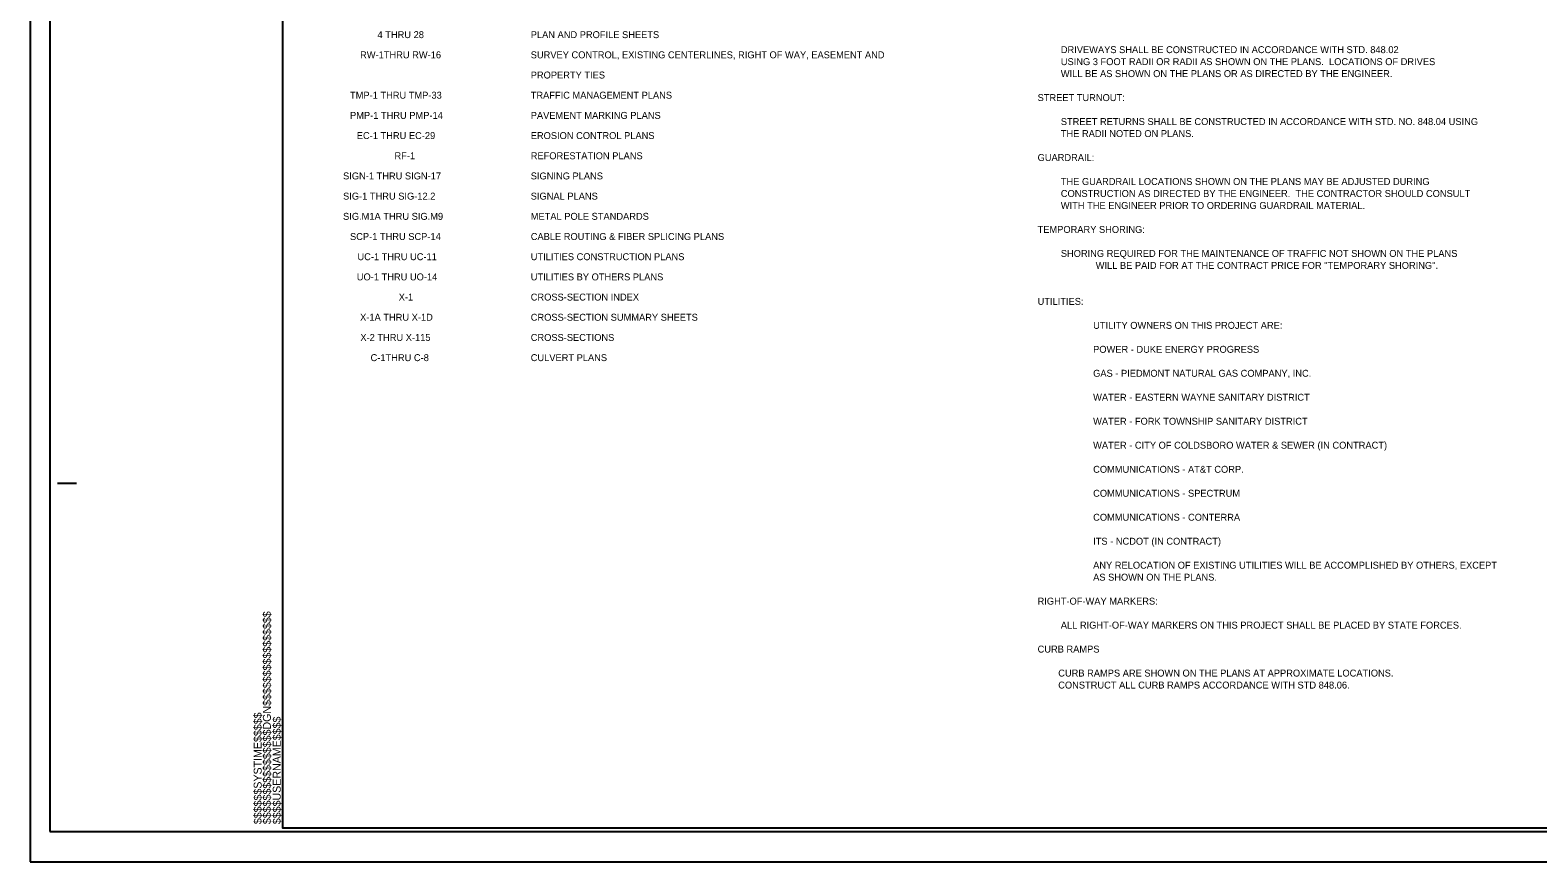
# Model space of a CAD drawing. Extents: x 1877070 to 1879304, y 464355 to 465670.
# Drawn here: x 1877070 to 1878265, y 464355 to 465014 of the extents above; entities that cross this region are included whole.
import ezdxf

# ---------------------------------------------------------------- set-up
doc = ezdxf.new("R2010")
doc.units = 0
for name, color, linetype in [('Prop AutoTurn Projected Path', 7, 'Continuous'), ('Prop Horizontal Alignment', 7, 'Continuous'), ('Prop Lane Lines', 7, 'Continuous'), ('Scratch_Level_0', 7, 'Continuous')]:
    doc.layers.add(name, color=color, linetype=linetype)

msp = doc.modelspace()

# ---------------------------------------------------------------- linework, layer by layer
at = {"layer": 'Prop AutoTurn Projected Path'}
msp.add_lwpolyline([(1877070, 464355.1), (1879090.8, 464355.1), (1879090.8, 465669.5), (1877070, 465669.5)], close=True, dxfattribs=at)
at = {"layer": 'Prop Lane Lines'}
msp.add_lwpolyline([(1877085.6, 464379.1), (1879085.4, 464379.1), (1879085.4, 465645.5), (1877085.6, 465645.5)], close=True, dxfattribs=at)
at = {"layer": 'Scratch_Level_0'}
for p, q in [((1877091.6, 464655.2), (1877106.6, 464655.2)), ((1877269.8, 464382.1), (1877269.8, 464382.1))]:
    msp.add_line(p, q, dxfattribs=at)
msp.add_lwpolyline([(1879070.4, 465642.5), (1877269.8, 465642.5), (1877269.8, 464382.1), (1879070.4, 464382.1)], close=True, dxfattribs=at)

# ---------------------------------------------------------------- texts
at = {"layer": 'Prop Horizontal Alignment'}
for s, p in [('4 THRU 28', (1877345.2, 465008)), ('PLAN AND PROFILE SHEETS', (1877466.6, 465008)), ('RW-1THRU RW-16', (1877331.4, 464992)), ('SURVEY CONTROL, EXISTING CENTERLINES, RIGHT OF WAY, EASEMENT AND ', (1877466.6, 464992)), ('         USING 3 FOOT RADII OR RADII AS SHOWN ON THE PLANS.  LOCATIONS OF DRIVES', (1877868.2, 464986.6)), ('         DRIVEWAYS SHALL BE CONSTRUCTED IN ACCORDANCE WITH STD. 848.02', (1877868.2, 464996.1)), ('PROPERTY TIES', (1877466.6, 464976)), ('         WILL BE AS SHOWN ON THE PLANS OR AS DIRECTED BY THE ENGINEER.  ', (1877868.2, 464977.1)), ('TMP-1 THRU TMP-33', (1877323.4, 464960)), ('TRAFFIC MANAGEMENT PLANS', (1877466.6, 464960)), ('STREET TURNOUT:  ', (1877868.2, 464958.1)), ('PMP-1 THRU PMP-14', (1877323.4, 464944)), ('PAVEMENT MARKING PLANS', (1877466.6, 464944)), ('         STREET RETURNS SHALL BE CONSTRUCTED IN ACCORDANCE WITH STD. NO. 848.04 USING ', (1877868.2, 464939.1)), ('EC-1 THRU EC-29', (1877328.8, 464928)), ('EROSION CONTROL PLANS', (1877466.6, 464928)), ('         THE RADII NOTED ON PLANS.  ', (1877868.2, 464929.6)), (' RF-1', (1877356.6, 464912)), ('REFORESTATION PLANS', (1877466.6, 464912)), ('GUARDRAIL:  ', (1877868.2, 464910.6)), ('SIGN-1 THRU SIGN-17', (1877317.9, 464896)), ('SIGNING PLANS', (1877466.6, 464896)), ('         THE GUARDRAIL LOCATIONS SHOWN ON THE PLANS MAY BE ADJUSTED DURING ', (1877868.2, 464891.6)), ('SIG-1 THRU SIG-12.2', (1877317.9, 464880)), ('SIGNAL PLANS', (1877466.6, 464880)), ('         CONSTRUCTION AS DIRECTED BY THE ENGINEER.  THE CONTRACTOR SHOULD CONSULT', (1877868.2, 464882.1)), ('         WITH THE ENGINEER PRIOR TO ORDERING GUARDRAIL MATERIAL.', (1877868.2, 464872.6)), ('SIG.M1A THRU SIG.M9', (1877317.9, 464864)), ('METAL POLE STANDARDS', (1877466.6, 464864)), ('SCP-1 THRU SCP-14', (1877323.4, 464848)), ('CABLE ROUTING & FIBER SPLICING PLANS', (1877466.6, 464848)), ('TEMPORARY SHORING:  ', (1877868.2, 464853.6)), ('UC-1 THRU UC-11', (1877329.3, 464832)), ('UTILITIES CONSTRUCTION PLANS', (1877466.6, 464832)), ('         SHORING REQUIRED FOR THE MAINTENANCE OF TRAFFIC NOT SHOWN ON THE PLANS ', (1877868.2, 464834.6)), (' WILL BE PAID FOR AT THE CONTRACT PRICE FOR "TEMPORARY SHORING".', (1877912.2, 464825.1)), ('UO-1 THRU UO-14', (1877328.8, 464816)), ('UTILITIES BY OTHERS PLANS', (1877466.6, 464816)), ('X-1', (1877362, 464800)), ('CROSS-SECTION INDEX', (1877466.6, 464800)), ('UTILITIES:  ', (1877868.2, 464796.6)), ('X-1A THRU X-1D', (1877331.4, 464784)), ('CROSS-SECTION SUMMARY SHEETS', (1877466.6, 464784)), ('UTILITY OWNERS ON THIS PROJECT ARE:', (1877912.2, 464777.6)), ('X-2 THRU X-115', (1877331.6, 464768)), ('CROSS-SECTIONS', (1877466.6, 464768)), ('POWER - DUKE ENERGY PROGRESS', (1877912.2, 464758.6)), ('C-1THRU C-8', (1877339.7, 464752)), ('CULVERT PLANS', (1877466.6, 464752)), ('GAS - PIEDMONT NATURAL GAS COMPANY, INC.', (1877912.2, 464739.6)), ('WATER - EASTERN WAYNE SANITARY DISTRICT', (1877912.2, 464720.6)), ('WATER - FORK TOWNSHIP SANITARY DISTRICT', (1877912.2, 464701.6)), ('WATER - CITY OF COLDSBORO WATER & SEWER (IN CONTRACT)', (1877912.2, 464682.6)), ('COMMUNICATIONS - AT&T CORP.', (1877912.2, 464663.5)), ('COMMUNICATIONS - SPECTRUM', (1877912.2, 464644.5)), ('COMMUNICATIONS - CONTERRA', (1877912.2, 464625.5)), ('ITS - NCDOT (IN CONTRACT)', (1877912.2, 464606.5)), ('ANY RELOCATION OF EXISTING UTILITIES WILL BE ACCOMPLISHED BY OTHERS, EXCEPT ', (1877912.2, 464587.5)), ('AS SHOWN ON THE PLANS.  ', (1877912.2, 464578)), ('RIGHT-OF-WAY MARKERS:  ', (1877868.2, 464559)), ('         ALL RIGHT-OF-WAY MARKERS ON THIS PROJECT SHALL BE PLACED BY STATE FORCES.  ', (1877868.2, 464540)), ('CURB RAMPS', (1877868.2, 464521)), ('        CURB RAMPS ARE SHOWN ON THE PLANS AT APPROXIMATE LOCATIONS.', (1877868.2, 464502)), ('        CONSTRUCT ALL CURB RAMPS ACCORDANCE WITH STD 848.06.', (1877868.2, 464492.5))]:
    msp.add_text(s, height=5.5, dxfattribs=at).set_placement(p)
at = {"layer": 'Scratch_Level_0'}
for s, p in [('$$$$$$$$$$$$$$$$DGN$$$$$$$$$$$$$$$$', (1877260.7, 464385)), ('$$$$$$SYSTIME$$$$$', (1877253.4, 464385)), ('$$$$USERNAME$$$$', (1877268.5, 464385))]:
    msp.add_text(s, height=6.302, rotation=90, dxfattribs=at).set_placement(p)

doc.saveas('drawing.dxf')
